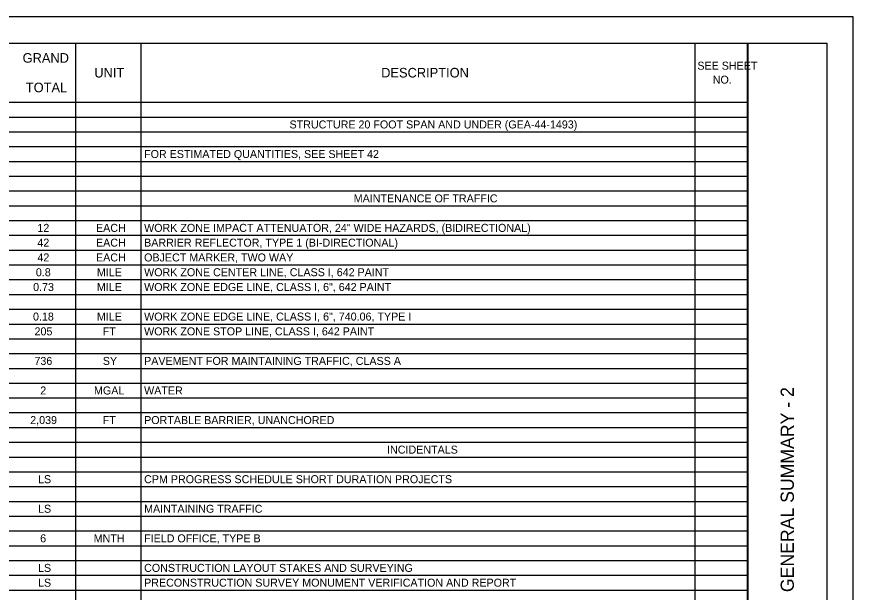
# Model space of a CAD drawing. Extents: x -50.3 to 36.4, y 0 to 22.5.
# Drawn here: x 18.16 to 34, y 11.1 to 22 of the extents above; entities that cross this region are included whole.
import ezdxf

# ---------------------------------------------------------------- set-up
doc = ezdxf.new("R2010")
doc.units = 0
for name, color, linetype in [('SH_Border', 7, 'Continuous'), ('SH_Cut_Line', 7, 'Continuous'), ('SH_Data', 7, 'Continuous'), ('SH_Text', 7, 'Continuous')]:
    doc.layers.add(name, color=color, linetype=linetype)

msp = doc.modelspace()

# ---------------------------------------------------------------- linework, layer by layer
at = {"layer": 'SH_Border'}
msp.add_line((32, 0.5), (32, 21.5), dxfattribs=at)
msp.add_lwpolyline([(1.5, 21.5), (33.5, 21.5), (33.5, 0.5), (1.5, 0.5)], close=True, dxfattribs=at)
at = {"layer": 'SH_Cut_Line'}
msp.add_lwpolyline([(0, 0), (34, 0), (34, 22), (0, 22)], close=True, dxfattribs=at)
at = {"layer": 'SH_Data'}
for p, q in [((1.5, 21.5), (32.001, 21.5)), ((19.27, 21.5), (19.27, 0.502)), ((20.506, 21.5), (20.506, 0.502)), ((30.997, 21.5), (30.997, 0.502)), ((32.001, 21.5), (32.001, 0.502)), ((1.5, 20.38), (32.001, 20.38)), ((1.5, 20.1), (32.001, 20.1)), ((1.5, 19.82), (32.001, 19.82)), ((1.5, 19.54), (32.001, 19.54)), ((1.5, 19.26), (32.001, 19.26)), ((1.5, 18.98), (32.001, 18.98)), ((1.5, 18.7), (32.001, 18.7)), ((1.5, 18.42), (32.001, 18.42)), ((1.5, 18.14), (32.001, 18.14)), ((1.5, 17.86), (32.001, 17.86)), ((1.5, 17.58), (32.001, 17.58)), ((1.5, 17.3), (32.001, 17.3)), ((1.5, 17.02), (32.001, 17.02)), ((1.5, 16.74), (32.001, 16.74)), ((1.5, 16.46), (32.001, 16.46)), ((1.5, 16.18), (32.001, 16.18)), ((1.5, 15.9), (32.001, 15.9)), ((1.5, 15.62), (32.001, 15.62)), ((1.5, 15.34), (32.001, 15.34)), ((1.5, 15.061), (32.001, 15.061)), ((1.5, 14.781), (32.001, 14.781)), ((1.5, 14.501), (32.001, 14.501)), ((1.5, 14.221), (32.001, 14.221)), ((1.5, 13.941), (32.001, 13.941)), ((1.5, 13.661), (32.001, 13.661)), ((1.5, 13.381), (32.001, 13.381)), ((1.5, 13.101), (32.001, 13.101)), ((1.5, 12.821), (32.001, 12.821)), ((1.5, 12.541), (32.001, 12.541)), ((1.5, 12.261), (32.001, 12.261)), ((1.5, 11.981), (32.001, 11.981)), ((1.5, 11.701), (32.001, 11.701)), ((1.5, 11.421), (32.001, 11.421)), ((1.5, 11.141), (32.001, 11.141))]:
    msp.add_line(p, q, dxfattribs=at)

# ---------------------------------------------------------------- texts
msp.add_text('GENERAL SUMMARY - 2', height=0.25, rotation=90, dxfattribs=at).set_placement((32.875, 11.102))
at = {"layer": 'SH_Text'}
for s, height, p in [('GRAND', 0.1818, (18.27, 21.129)), ('SEE SHEET ', 0.1515, (31.048, 20.997)), ('UNIT', 0.1818, (19.628, 20.849)), ('DESCRIPTION', 0.18182, (25.06, 20.849)), ('TOTAL', 0.1818, (18.331, 20.569)), ('NO.', 0.1515, (31.339, 20.732)), ('STRUCTURE 20 FOOT SPAN AND UNDER (GEA-44-1493)', 0.15152, (23.325, 19.884)), ('FOR ESTIMATED QUANTITIES, SEE SHEET 42', 0.15152, (20.571, 19.324)), ('MAINTENANCE OF TRAFFIC', 0.15152, (24.54, 18.484)), ('12', 0.1515, (18.55, 17.925)), ('EACH', 0.1515, (19.66, 17.925)), ('WORK ZONE IMPACT ATTENUATOR, 24" WIDE HAZARDS, (BIDIRECTIONAL)', 0.15152, (20.571, 17.925)), ('42', 0.1515, (18.55, 17.645)), ('EACH', 0.1515, (19.66, 17.645)), ('BARRIER REFLECTOR, TYPE 1 (BI-DIRECTIONAL)', 0.15152, (20.571, 17.645)), ('42', 0.1515, (18.55, 17.365)), ('EACH', 0.1515, (19.66, 17.365)), ('OBJECT MARKER, TWO WAY', 0.15152, (20.571, 17.365)), ('0.8', 0.1515, (18.521, 17.085)), ('MILE', 0.1515, (19.677, 17.085)), ('WORK ZONE CENTER LINE, CLASS I, 642 PAINT', 0.15152, (20.571, 17.085)), ('0.73', 0.1515, (18.469, 16.805)), ('MILE', 0.1515, (19.677, 16.805)), ('WORK ZONE EDGE LINE, CLASS I, 6", 642 PAINT', 0.15152, (20.571, 16.805)), ('0.18', 0.1515, (18.467, 16.245)), ('MILE', 0.1515, (19.677, 16.245)), ('WORK ZONE EDGE LINE, CLASS I, 6", 740.06, TYPE I', 0.15152, (20.571, 16.245)), ('205', 0.1515, (18.496, 15.965)), ('FT', 0.1515, (19.787, 15.965)), ('WORK ZONE STOP LINE, CLASS I, 642 PAINT', 0.15152, (20.571, 15.965)), ('736', 0.1515, (18.494, 15.405)), ('SY', 0.1515, (19.789, 15.405)), ('PAVEMENT FOR MAINTAINING TRAFFIC, CLASS A', 0.15152, (20.571, 15.405)), ('2', 0.152, (18.604, 14.845)), ('MGAL', 0.1515, (19.622, 14.845)), ('WATER', 0.1515, (20.571, 14.845)), ('2,039', 0.1515, (18.414, 14.285)), ('FT', 0.1515, (19.787, 14.285)), ('PORTABLE BARRIER, UNANCHORED', 0.15152, (20.571, 14.285)), ('INCIDENTALS', 0.15152, (25.172, 13.725)), ('LS', 0.1515, (18.562, 13.165)), ('CPM PROGRESS SCHEDULE SHORT DURATION PROJECTS', 0.15152, (20.571, 13.165)), ('LS', 0.1515, (18.562, 12.605)), ('MAINTAINING TRAFFIC', 0.15152, (20.571, 12.605)), ('6', 0.152, (18.603, 12.045)), ('FIELD OFFICE, TYPE B', 0.15152, (20.571, 12.045)), ('MNTH', 0.1515, (19.616, 12.045)), ('LS', 0.1515, (18.562, 11.485)), ('CONSTRUCTION LAYOUT STAKES AND SURVEYING', 0.15152, (20.571, 11.485)), ('LS', 0.1515, (18.562, 11.205)), ('PRECONSTRUCTION SURVEY MONUMENT VERIFICATION AND REPORT', 0.15152, (20.571, 11.205))]:
    msp.add_text(s, height=height, dxfattribs=at).set_placement(p)

doc.saveas('drawing.dxf')
